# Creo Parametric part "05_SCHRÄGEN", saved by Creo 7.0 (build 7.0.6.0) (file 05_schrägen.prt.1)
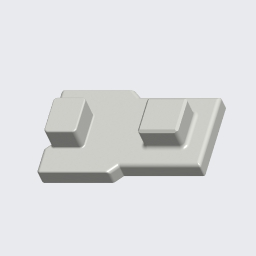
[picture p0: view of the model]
Materials in the file: S235JRG2

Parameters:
  PTC_MATERIAL_NAME = "S235JRG2"
  BENENNUNG = "XXX"
  DATUM = "XX.XX.XX"
  ERSTELLER = "ARINDA"
  TEILETYP = "Fertigungsteil"
  SELECT_EN_NAME = "S235JRG2"
  SELECT_DIN_NAME = "RSt37-2"
  SELECT_DIN_NUMBER = "1.0038"
  SELECT_ASTM_NAME = "A 283 M Grade 2"
  MATERIAL_GROUP = "ME_ST_Baustahl"
  STANDARD_EN_DELIVERYSPEC = "DIN EN 10025"
  STANDARD_DIN_DELIVERYSPEC = "DIN 17100"

Other parameters: MASSE

Created from: ARINDA-STARTTEIL.PRT

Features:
  1. coordinate system "CS0"
  2. datum plane "DTM1", "T_RECHTS_Y-Z"
  3. datum plane "DTM2", "T_OBEN_X-Z"
  4. datum plane "DTM3", "T_VORNE_X-Y"
  5. datum axis "T_X-ACHSE"
  6. datum axis "A_1"
  7. datum axis "A_2"
  8. imported feature "Import-ke ID 40"

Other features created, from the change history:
  feature "Schräge 1"
  feature "Schräge 2"
  feature "Fase Editieren 1"

Other named items: T_BASIC, T_Y-ACHSE, T_Z-ACHSE

Layers: 00_STD-ACHSEN, 00_STD-EBENEN, 00_STD-KOORDSYS, SAMMELFLÄCHEN, VOLUMENGEOMETRIE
